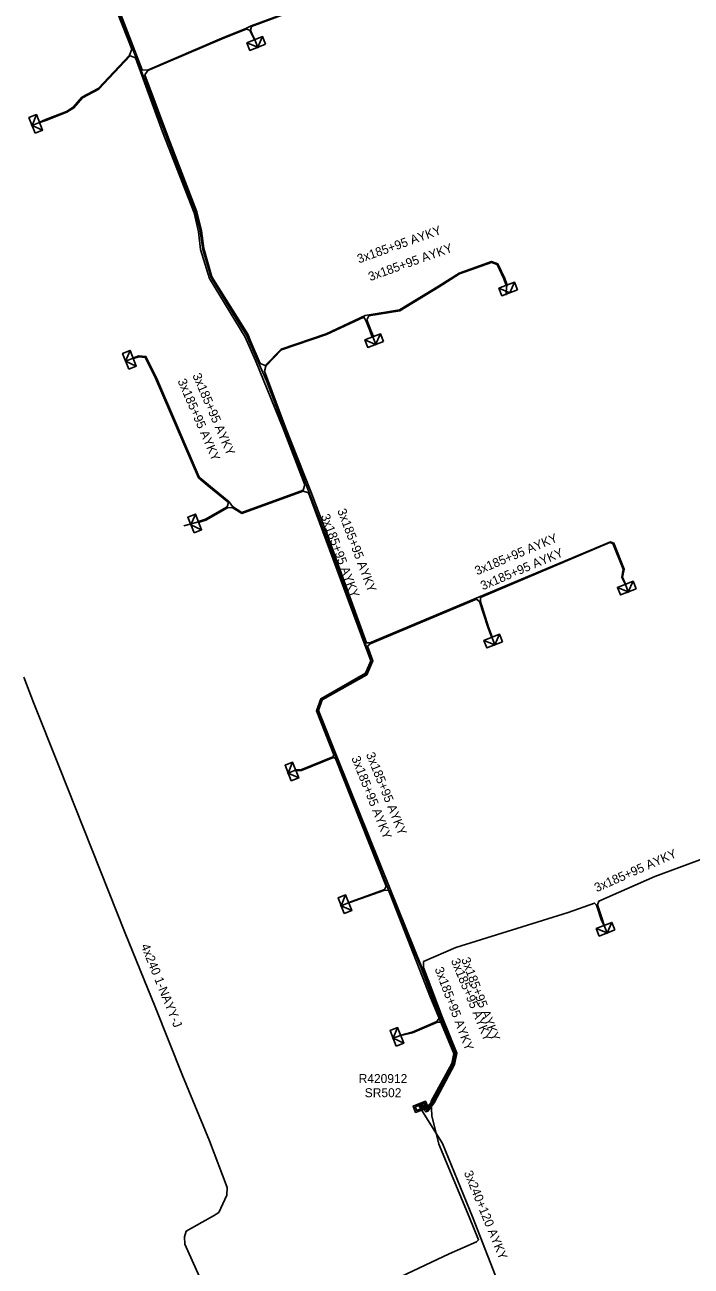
# Model space of a CAD drawing. Extents: x -540028 to -538776, y -1157064 to -1155670.
# Drawn here: x -539895.6 to -539821.3, y -1156179 to -1156040.4 of the extents above; entities that cross this region are included whole.
import ezdxf

# ---------------------------------------------------------------- set-up
doc = ezdxf.new("R2010")
doc.units = 0
for name, color, linetype in [('Vrstva 2', 7, 'Continuous'), ('Vrstva 28', 7, 'Continuous'), ('Vrstva 29', 7, 'Continuous'), ('Vrstva 30', 7, 'Continuous'), ('Vrstva 31', 7, 'Continuous'), ('Vrstva 5', 7, 'Continuous'), ('Vrstva 59', 7, 'Continuous'), ('Vrstva 6', 7, 'Continuous')]:
    doc.layers.add(name, color=color, linetype=linetype)

# ---------------------------------------------------------------- blocks, each defined once
blk = doc.blocks.new('132')
at = {"layer": 'Vrstva 2'}
for points in [[(-1.5, 1.5), (1.5, 1.5), (1.5, 0), (-1.5, 0)], [(-1.1, 1.2), (1.1, 1.2), (1.1, 0.3), (-1.1, 0.3)]]:
    blk.add_lwpolyline(points, close=True, dxfattribs=at)
blk = doc.blocks.new('23')
at = {"layer": 'Vrstva 2'}
blk.add_lwpolyline([(1.875, -1.8), (-1.875, -1.8), (-1.875, 0), (1.875, 0)], close=True, dxfattribs=at)
blk.add_lwpolyline([(1.875, 0), (0, -1.8), (-1.875, 0)], dxfattribs=at)

msp = doc.modelspace()

# ---------------------------------------------------------------- linework, layer by layer
at = {"layer": 'Vrstva 5'}
for points in [[(-539876.2, -1156095.91), (-539876.11, -1156095.83), (-539875.44, -1156095.61), (-539873, -1156094.21), (-539872.87, -1156093.74), (-539875.23, -1156091.82), (-539876.21, -1156090.97), (-539881, -1156079.86), (-539882.14, -1156077.54), (-539882.87, -1156077.48), (-539883.45, -1156077.66), (-539883.5, -1156077.64), (-539883.47, -1156077.59), (-539882.86, -1156077.38), (-539882.07, -1156077.44), (-539880.91, -1156079.82), (-539876.12, -1156090.91), (-539872.8, -1156093.66), (-539872.4, -1156094.2), (-539871.38, -1156094.85), (-539864.55, -1156092.38), (-539864.34, -1156091.77), (-539866.77, -1156085.5), (-539869.85, -1156077.88), (-539870.99, -1156075.29), (-539874.98, -1156068.74), (-539875.97, -1156065.52), (-539876.21, -1156063.53), (-539876.7, -1156061.42), (-539880.23, -1156052.35), (-539883.24, -1156044.11), (-539883.83, -1156043.87), (-539887.33, -1156047.61), (-539889.14, -1156048.58), (-539890.11, -1156049.69), (-539890.9, -1156050.18), (-539893.24, -1156051.09), (-539893.91, -1156051.32), (-539893.94, -1156051.31), (-539893.93, -1156051.28), (-539893.26, -1156051), (-539890.94, -1156050.08), (-539890.17, -1156049.61), (-539889.21, -1156048.5), (-539887.39, -1156047.53), (-539883.9, -1156043.8), (-539883.66, -1156043.14), (-539886.91, -1156034.8)], [(-539886.66, -1156035.08), (-539882.13, -1156046.77), (-539876.53, -1156061.36), (-539876.04, -1156063.44), (-539875.72, -1156065.5), (-539874.79, -1156068.62), (-539871.35, -1156074.32), (-539870.86, -1156075.05), (-539868.64, -1156080.17), (-539861.56, -1156098.69), (-539856.9, -1156111.42), (-539857.49, -1156112.89), (-539862.5, -1156115.68), (-539862.96, -1156116.98), (-539855.12, -1156136.71), (-539850.35, -1156148.98), (-539847.73, -1156155.26), (-539847.95, -1156156.37), (-539850.27, -1156160.58), (-539850.19, -1156162.2), (-539849.42, -1156165.36), (-539846.02, -1156173.46), (-539844.98, -1156176.03), (-539845.21, -1156176.28), (-539848.27, -1156177.59), (-539859.05, -1156182.72)], [(-539886.51, -1156035), (-539882.48, -1156045.43), (-539881.9, -1156045.48), (-539873.6, -1156041.92), (-539870.92, -1156040.82), (-539870.33, -1156040.53), (-539858.6, -1156036.19)], [(-539860.58, -1156036.96), (-539870.3, -1156040.6), (-539870.41, -1156041.01), (-539870.21, -1156041.47), (-539869.91, -1156042.07), (-539869.93, -1156042.09), (-539869.95, -1156042.09), (-539870.25, -1156041.5), (-539870.48, -1156041.03), (-539870.89, -1156040.91), (-539873.56, -1156041.98), (-539881.85, -1156045.54), (-539882.21, -1156045.99), (-539879.54, -1156053.06), (-539876.39, -1156061.31), (-539875.89, -1156063.42), (-539875.63, -1156065.4), (-539874.71, -1156068.54), (-539870.7, -1156074.95), (-539870.38, -1156075.79), (-539869.35, -1156078.21), (-539868.78, -1156078.44), (-539866.99, -1156076.63), (-539861.98, -1156074.9), (-539857.63, -1156072.88), (-539853.79, -1156072.25), (-539849.44, -1156069.61), (-539847.13, -1156068.13), (-539843.55, -1156066.85), (-539842.83, -1156067.09), (-539842.05, -1156068.73), (-539841.81, -1156069.37), (-539841.83, -1156069.49)], [(-539841.83, -1156069.49), (-539841.92, -1156069.4), (-539842.14, -1156068.77), (-539842.91, -1156067.17), (-539843.55, -1156066.95), (-539847.09, -1156068.22), (-539849.36, -1156069.68), (-539853.75, -1156072.35), (-539857.23, -1156072.91), (-539857.45, -1156073.37), (-539857, -1156074.5), (-539856.73, -1156075.15), (-539856.78, -1156075.26), (-539856.87, -1156075.16), (-539857.09, -1156074.54), (-539857.54, -1156073.41), (-539857.77, -1156073.05), (-539861.95, -1156075), (-539866.94, -1156076.71), (-539868.71, -1156078.51), (-539868.85, -1156079.08), (-539866.49, -1156085.38), (-539863.69, -1156092.51), (-539861.38, -1156098.62), (-539857.48, -1156109.42), (-539857.12, -1156109.4), (-539844.81, -1156104.23), (-539830.28, -1156098.13), (-539829.9, -1156098.27), (-539828.74, -1156101.18), (-539828.91, -1156102.09), (-539828.59, -1156102.84), (-539828.6, -1156102.88), (-539828.64, -1156102.86), (-539829, -1156102.11), (-539828.84, -1156101.19), (-539830.02, -1156098.31), (-539830.32, -1156098.21), (-539844.76, -1156104.33), (-539844.75, -1156104.78), (-539843.85, -1156107.64), (-539843.46, -1156108.73), (-539843.5, -1156108.79), (-539843.55, -1156108.75), (-539843.95, -1156107.67), (-539844.87, -1156104.81), (-539845.21, -1156104.54), (-539857.07, -1156109.5), (-539857.35, -1156109.79), (-539856.77, -1156111.4), (-539857.42, -1156112.96), (-539862.43, -1156115.78), (-539862.84, -1156116.96), (-539860.72, -1156122.29), (-539854.79, -1156136.97), (-539851.29, -1156145.64), (-539849.19, -1156151.21), (-539847.55, -1156155.21), (-539847.79, -1156156.41), (-539850.07, -1156160.66), (-539850.76, -1156161.59), (-539851.61, -1156160.87)], [(-539851.45, -1156160.81), (-539850.75, -1156161.31), (-539850.11, -1156160.52), (-539847.9, -1156156.41), (-539847.66, -1156155.24), (-539849.12, -1156151.73), (-539849.57, -1156151.76), (-539852.34, -1156152.95), (-539853.65, -1156153.23), (-539853.67, -1156153.22), (-539853.66, -1156153.19), (-539852.38, -1156152.86), (-539849.63, -1156151.68), (-539849.3, -1156151.2), (-539851.38, -1156145.67), (-539854.93, -1156137.06), (-539855.43, -1156137.02), (-539859.45, -1156138.43), (-539859.47, -1156138.42), (-539859.46, -1156138.39), (-539855.46, -1156136.94), (-539855.29, -1156136.57), (-539860.93, -1156122.32), (-539861.16, -1156122.19), (-539864.73, -1156123.65), (-539865.33, -1156123.65), (-539865.38, -1156123.61), (-539865.36, -1156123.58), (-539864.78, -1156123.57), (-539861.23, -1156122.12), (-539861.1, -1156121.89), (-539863.04, -1156117.01), (-539862.56, -1156115.64), (-539857.57, -1156112.78), (-539856.99, -1156111.41), (-539857.65, -1156109.64), (-539863.94, -1156092.65), (-539864.52, -1156092.48), (-539871.39, -1156094.96), (-539872.45, -1156094.29), (-539872.97, -1156094.33), (-539875.39, -1156095.7), (-539876.08, -1156095.94), (-539876.2, -1156095.91)], [(-539895.7, -1156113.23), (-539894.6, -1156116.08), (-539891.75, -1156123.24), (-539888.09, -1156132.42), (-539884.37, -1156141.83), (-539881.04, -1156150.04), (-539878.01, -1156157.7), (-539875, -1156164.99), (-539873, -1156170.2), (-539873.05, -1156171.04), (-539873.96, -1156173), (-539874.52, -1156173.35), (-539875.81, -1156174.07), (-539877.6, -1156175.09), (-539877.76, -1156175.7), (-539877.72, -1156176.54), (-539873.98, -1156184.89)], [(-539851.69, -1156160.9), (-539850.86, -1156161.77), (-539850.63, -1156161.68), (-539849.94, -1156160.74), (-539847.65, -1156156.46), (-539847.39, -1156155.2), (-539849.05, -1156151.15), (-539851.13, -1156145.63), (-539851.1, -1156144.98), (-539847.5, -1156143.43), (-539834.98, -1156139.5), (-539832.06, -1156138.45), (-539831.82, -1156138.69), (-539831.25, -1156140.38), (-539830.98, -1156140.95), (-539831.16, -1156140.34), (-539831.72, -1156138.65), (-539831.57, -1156138.23), (-539825.3, -1156135.47), (-539817.59, -1156132.61)], [(-539834.5, -1156197.03), (-539833.31, -1156197.31), (-539831.32, -1156196.41), (-539831.41, -1156195.48), (-539834.3, -1156188.62), (-539837.34, -1156186.81), (-539842.25, -1156182.27), (-539845.64, -1156173.48), (-539848.98, -1156165.28), (-539851.72, -1156160.92)]]:
    msp.add_lwpolyline(points, dxfattribs=at)
at = {"layer": 'Vrstva 59'}
for points in [[(-539869.93, -1156042.09), (-539869.56, -1156043.02)], [(-539893.94, -1156051.31), (-539894.87, -1156051.68)], [(-539841.83, -1156069.49), (-539841.93, -1156070.61)], [(-539856.78, -1156075.26), (-539856.41, -1156076.19)], [(-539883.5, -1156077.64), (-539884.43, -1156078.01)], [(-539876.2, -1156095.91), (-539877.84, -1156096.35)], [(-539828.6, -1156102.88), (-539828.24, -1156103.81)], [(-539843.5, -1156108.79), (-539843.13, -1156109.72)], [(-539865.38, -1156123.61), (-539866.31, -1156123.98)], [(-539859.47, -1156138.42), (-539860.4, -1156138.78)], [(-539830.98, -1156140.95), (-539830.61, -1156141.88)], [(-539853.67, -1156153.22), (-539854.6, -1156153.58)]]:
    msp.add_lwpolyline(points, dxfattribs=at)

# ---------------------------------------------------------------- block references
at = {"layer": 'Vrstva 28', "xscale": 0.5, "yscale": 0.5, "rotation": -158.4351194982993}
msp.add_blockref('132', (-539851.58, -1156160.84), dxfattribs=at)
at = {"layer": 'Vrstva 31'}
for p, xscale, yscale, rotation in [((-539869.93, -1156042.09), 0.5000000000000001, 0.4999999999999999, 21.59732777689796), ((-539893.94, -1156051.31), 0.5000000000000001, 0.4999999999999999, -68.27245828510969), ((-539841.83, -1156069.49), 0.5, 0.5, 21.339988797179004), ((-539856.78, -1156075.26), 0.5, 0.5000000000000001, 21.3370417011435), ((-539883.5, -1156077.64), 0.5, 0.5, -68.33281395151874), ((-539876.21, -1156095.91), 0.5000000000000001, 0.4999999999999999, -68.3263027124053), ((-539828.61, -1156102.88), 0.49999999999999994, 0.5000000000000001, 21.521352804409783), ((-539843.5, -1156108.79), 0.49999999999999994, 0.5000000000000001, 21.518077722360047), ((-539865.38, -1156123.61), 0.49999999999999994, 0.5000000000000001, -68.51479999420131), ((-539859.47, -1156138.42), 0.5, 0.5, -68.4734362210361), ((-539830.98, -1156140.95), 0.5, 0.5, 21.58793881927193), ((-539853.67, -1156153.22), 0.5, 0.49999999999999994, -68.54662496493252)]:
    msp.add_blockref('23', p, dxfattribs=dict(at, xscale=xscale, yscale=yscale, rotation=rotation))

# ---------------------------------------------------------------- texts
at = {"layer": 'Vrstva 29'}
msp.add_text('R420912', height=1, dxfattribs=at).set_placement((-539858.35, -1156158.54))
at = {"layer": 'Vrstva 30'}
msp.add_text('SR502', height=1, rotation=0.024, dxfattribs=at).set_placement((-539857.67, -1156160.12))
at = {"layer": 'Vrstva 6'}
for s, rotation, p in [('3x185+95 AYKY', 19.682, (-539858.31, -1156067.06)), ('3x185+95 AYKY', 19.693, (-539857.06, -1156069.04)), ('3x185+95 AYKY', 293.332, (-539878.56, -1156080.17)), ('3x185+95 AYKY', 293.334, (-539876.91, -1156079.55)), ('3x185+95 AYKY', 290.321, (-539862.58, -1156095.23)), ('3x185+95 AYKY', 290.685, (-539860.75, -1156094.63)), ('3x185+95 AYKY', 22.789, (-539845.15, -1156101.88)), ('3x185+95 AYKY', 22.97, (-539844.51, -1156103.55)), ('3x185+95 AYKY', 291.615, (-539859.18, -1156122.26)), ('3x185+95 AYKY', 292.033, (-539857.55, -1156121.85)), ('3x185+95 AYKY', 23.726, (-539831.8, -1156137.25)), ('4x240 1-NAYY-J', 292.078, (-539882.66, -1156143.22)), ('3x185+95 AYKY', 292.34, (-539848.08, -1156144.86)), ('3x185+95 AYKY', 290.597, (-539846.93, -1156144.72)), ('3x185+95 AYKY', 290.605, (-539849.89, -1156145.8)), ('3x240+120 AYKY', 292.172, (-539846.63, -1156168.54))]:
    msp.add_text(s, height=1, rotation=rotation, dxfattribs=at).set_placement(p)

doc.saveas('drawing.dxf')
